Omron CX-Programmer project NewProject (CX-Programmer 8.01)

# PLC NewPLC1: CJ1M CPU11
I/O table (CPU CJ1M-CPU11): rack 0 slot 0 CJ1W-ID211; rack 0 slot 1 CJ1W-OC211; rack 0 slot 2 CJ1W-CT021

## Global symbols (name address type ; comment)
0.01 BOOL  ; Dip Switch To Input 1
0.03 BOOL  ; Dip Switch To Input 3
2000.00 BOOL  ; General Counter Manual Output Control
2000.01 BOOL  ; General Counter Manual Output Control
2000.15 BOOL  ; General Counter Automatic / Manual
2001.00 BOOL  ; General Counter Read Next Error
2002.00 BOOL  ; Counter 1 Open Gate
2002.01 BOOL  ; Counter 1 Close Gate
2002.02 BOOL  ; Counter 1 Load Preset Value
2002.03 BOOL  ; Counter 1 Reset Counter (Forced Reset) To Zero
2002.04 BOOL  ; Counter 1 Capture Counter Value
2002.05 BOOL  ; Counter 1 Enable Resetting For Z-Signal / Digital Input
2005.00 BOOL  ; Counter 2 Open Gate
2005.01 BOOL  ; Counter 2 Close Gate
2005.02 BOOL  ; Counter 2 Load Preset Value
2005.03 BOOL  ; Counter 2 Reset Counter (Forced Reset) To Zero
2005.04 BOOL  ; Counter 2 Capture Counter Value
2005.05 BOOL  ; Counter 2 Enable Resetting For Z-Signal / Digital Input
2016.00 BOOL  ; General Counter Input Status
2016.01 BOOL  ; General Counter Input Status
2019.00 BOOL  ; General Counter Global Error
2019.01 BOOL  ; General Counter Interrupts Pending
2019.02 BOOL  ; General Counter Data Transfer Busy
2019.03 BOOL  ; General Counter Data Transfer Completed
2019.04 BOOL  ; General Counter IA Blocks Overlap
2024.00 BOOL  ; Counter 1 Counter Overflow
2024.01 BOOL  ; Counter 1 Counter Underflow
2024.02 BOOL  ; Counter 1 Counter Running/Gate Open=1 / Counter Stopped/Gate Closed=0
2024.03 BOOL  ; Counter 1 Counting Direction, Down=0 / Up=1
2024.04 BOOL  ; Counter 1 Preset Activated
2024.05 BOOL  ; Counter 1 Reset Activated
2024.06 BOOL  ; Counter 1 Capture Activated
2024.07 BOOL  ; Counter 1 Z-Signal Activated
2024.10 BOOL  ; Counter 1 Rate Range 0
2024.11 BOOL  ; Counter 1 Rate Range 1
2024.15 BOOL  ; Counter 1 Simple Counter=1 / Circular/Linear Counter=0
2029.00 BOOL  ; Counter 2 Counter Overflow
2029.01 BOOL  ; Counter 2 Counter Underflow
2029.02 BOOL  ; Counter 2 Counter Running/Gate Open=1 / Counter Stopped/Gate Closed=0
2029.03 BOOL  ; Counter 2 Counting Direction, Down=0 / Up=1
2029.04 BOOL  ; Counter 2 Preset Activated
2029.05 BOOL  ; Counter 2 Reset Activated
2029.06 BOOL  ; Counter 2 Capture Activated
2029.07 BOOL  ; Counter 2 Z-Signal Activated
2029.10 BOOL  ; Counter 2 Rate Range 0
2029.11 BOOL  ; Counter 2 Rate Range 1
D5000 CHANNEL  ; Range 0 Lower Range Limit
D5002 CHANNEL  ; Range 0 Upper Range Limit
D5004 CHANNEL  ; Range 0 Output Pattern (To Set Which Output Are On)
D5006 CHANNEL  ; Range 1 Lower Range Limit
D5008 CHANNEL  ; Range 1 Upper Range Limit
D5010 CHANNEL  ; Range 1 Output Pattern (To Set Which Outputs Are On)
D5012 CHANNEL  ; Range 2 Lower Range Limit
D5014 CHANNEL  ; Range 2 Upper Range Limit
D5016 CHANNEL  ; Range 2 Output Pattern (To Set Which Outputs Are On)
D6000 CHANNEL  ; Range 0 Lower Range Limit From Touch Screen
D6002 CHANNEL  ; Range 0 Upper Range Limit From Touch Screen
D6004 CHANNEL  ; Range 0 Output Pattern (To Set Which Outputs Are On) From Touch Screen
D6006 CHANNEL  ; Range 1 Lower Range Limit From Touch Screen
D6008 CHANNEL  ; Range 1 Upper Range Limit From Touch Screen
D6010 CHANNEL  ; Range 1 Output Pattern (To Set Which Outputs Are On) From Touch Screen
D6012 CHANNEL  ; Range 2 Lower Range Limit From Touch Screen
D6014 CHANNEL  ; Range 2 Upper Range Limit From Touch Screen
D6016 CHANNEL  ; Range 2 Output Pattern (To Set Which Outputs Are On) From Touch Screen
W1.00 BOOL  ; Seal In Circuit For Range Data
W1.01 BOOL  ; Transfer Successful For Range Data
W1.04 BOOL  ; Data Has Been Successfully Written For Range Data
Counter1CounterValue 2022 DINT  ; Counter 1 Counter Value
Counter1PresetValue 2003 DINT  ; Counter 1 Preset Value
Counter1Ranges_ComparisonsValuesActive 2020 DINT  ; Counter 1 Ranges / Comparisons Values Active
Counter2CounterValue 2027 DINT  ; Counter 2 Counter Value
Counter2PresetValue 2006 DINT  ; Counter 2 Preset Value
Counter2Ranges_ComparisonsValuesActive 2025 DINT  ; Counter 2 Ranges / Comparisons Values Active
GeneralCounterErrorCode1 2017 UINT  ; General Counter Error Code 1
GeneralCounterErrorCode2 2018 UINT  ; General Counter Error Code 2
GeneralCounterOutputStatus 2014 DINT  ; General Counter Output Status

## Program NewProgram1 (cyclic task 0)
; ALL OF THESE ARE RESERVED / CT021 - CIO2000-CIO2039 & D20000-D20399 & D10000-D10319
Local symbols
cc1 UINT

### Section Section1

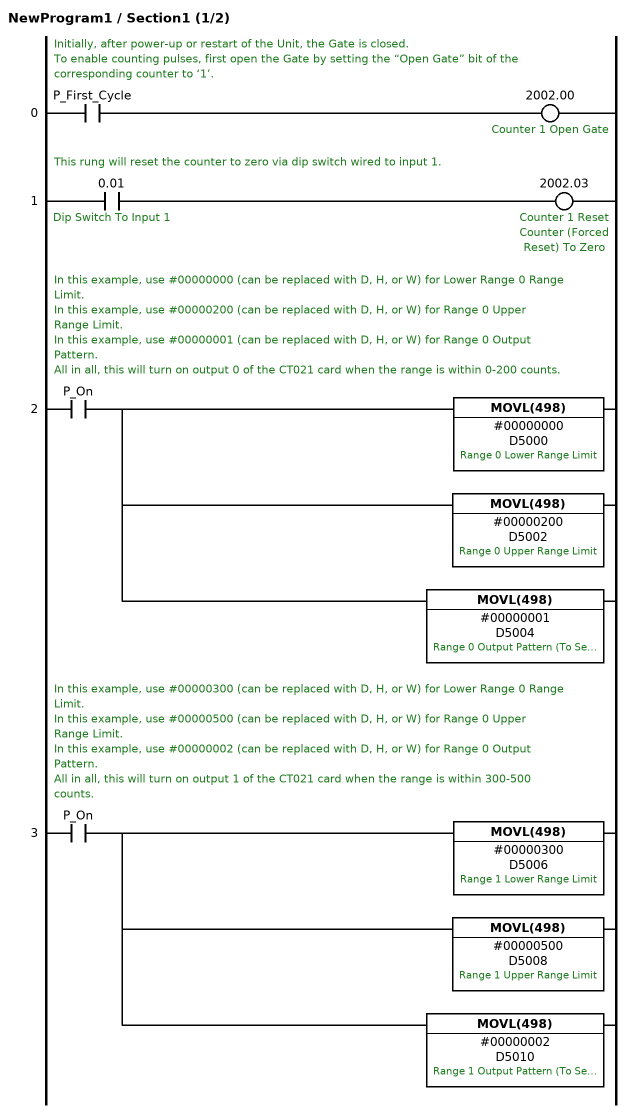
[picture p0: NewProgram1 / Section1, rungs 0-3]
; rung 0: Initially, after power-up or restart of the Unit, the Gate is closed. / To enable counting pulses, first open the Gate by setting the “Open Gate” bit of the corresponding counter to ‘1’.
LD P_First_Cycle
OUT 2002.00  ; Counter 1 Open Gate
; rung 1: This rung will reset the counter to zero via dip switch wired to input 1.
LD 0.01  ; Dip Switch To Input 1
OUT 2002.03  ; Counter 1 Reset Counter (Forced Reset) To Zero
; rung 2: In this example, use #00000000 (can be replaced with D, H, or W) for Lower Range 0 Range Limit. / In this example, use #00000200 (can be replaced with D, H, or W) for Range 0 Upper Range Limit. / In this example, use #00000001 (can be replaced with D, H, or W) for Range 0 Output Pattern. / All in all, this will turn on output 0 of the CT021 card when the range is within 0-200 counts.
LD P_On
MOVL(498) #00000000 D5000  ; Range 0 Lower Range Limit
MOVL(498) #00000200 D5002  ; Range 0 Upper Range Limit
MOVL(498) #00000001 D5004  ; Range 0 Output Pattern (To Set Which Output Are On)
; rung 3: In this example, use #00000300 (can be replaced with D, H, or W) for Lower Range 0 Range Limit. / In this example, use #00000500 (can be replaced with D, H, or W) for Range 0 Upper Range Limit. / In this example, use #00000002 (can be replaced with D, H, or W) for Range 0 Output Pattern. / All in all, this will turn on output 1 of the CT021 card when the range is within 300-500 counts.
LD P_On
MOVL(498) #00000300 D5006  ; Range 1 Lower Range Limit
MOVL(498) #00000500 D5008  ; Range 1 Upper Range Limit
MOVL(498) #00000002 D5010  ; Range 1 Output Pattern (To Set Which Outputs Are On)

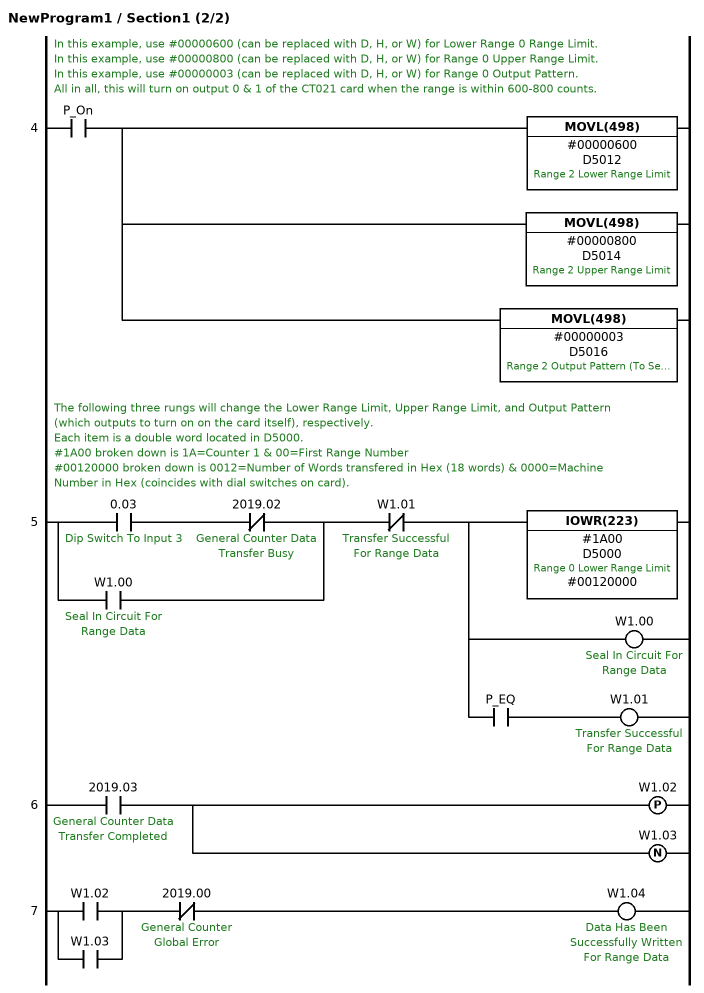
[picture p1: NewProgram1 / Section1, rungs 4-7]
; rung 4: In this example, use #00000600 (can be replaced with D, H, or W) for Lower Range 0 Range Limit. / In this example, use #00000800 (can be replaced with D, H, or W) for Range 0 Upper Range Limit. / In this example, use #00000003 (can be replaced with D, H, or W) for Range 0 Output Pattern. / All in all, this will turn on output 0 & 1 of the CT021 card when the range is within 600-800 counts.
LD P_On
MOVL(498) #00000600 D5012  ; Range 2 Lower Range Limit
MOVL(498) #00000800 D5014  ; Range 2 Upper Range Limit
MOVL(498) #00000003 D5016  ; Range 2 Output Pattern (To Set Which Outputs Are On)
; rung 5: The following three rungs will change the Lower Range Limit, Upper Range Limit, and Output Pattern (which outputs to turn on on the card itself), respectively. / Each item is a double word located in D5000. / #1A00 broken down is 1A=Counter 1 & 00=First Range Number / #00120000 broken down is 0012=Number of Words transfered in Hex (18 words) & 0000=Machine Number in Hex (coincides with dial switches on card).
LD 0.03  ; Dip Switch To Input 3
ANDNOT 2019.02  ; General Counter Data Transfer Busy
OR W1.00  ; Seal In Circuit For Range Data
ANDNOT W1.01  ; Transfer Successful For Range Data
IOWR(223) #1A00 D5000 #00120000  ; Range 0 Lower Range Limit
OUT W1.00  ; Seal In Circuit For Range Data
AND P_EQ
OUT W1.01  ; Transfer Successful For Range Data
; rung 6
LD 2019.03  ; General Counter Data Transfer Completed
DIFU(013) W1.02
DIFD(014) W1.03
; rung 7
LD W1.02
OR W1.03
ANDNOT 2019.00  ; General Counter Global Error
OUT W1.04  ; Data Has Been Successfully Written For Range Data

### Section END
; rung 0
END(001)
